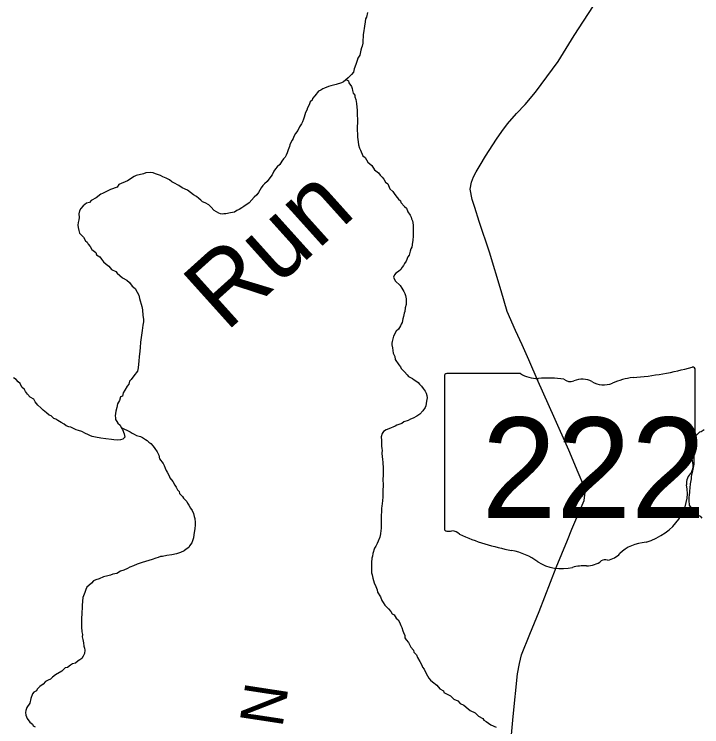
# Model space of a CAD drawing. Extents: x 0 to 34, y 0 to 22.
# Drawn here: x 4.746 to 5.649, y 14.474 to 15.409 of the extents above; entities that cross this region are included whole.
import ezdxf

# ---------------------------------------------------------------- set-up
doc = ezdxf.new("R2010")
doc.units = 0
for name, color, linetype in [('GM_X_Minor_River', 7, 'Continuous'), ('GM_X_Minor_River_Text', 7, 'Continuous'), ('GM_X_State_Location', 7, 'Continuous'), ('GM_X_State_Route', 7, 'Continuous'), ('GM_X_State_Shield', 7, 'Continuous'), ('GM_X_Township_Road_Text', 7, 'Continuous')]:
    doc.layers.add(name, color=color, linetype=linetype)

msp = doc.modelspace()

# ---------------------------------------------------------------- linework, layer by layer
at = {"layer": 'GM_X_Minor_River'}
for points in [[(5.20985, 15.4114), (5.20861, 15.40534), (5.20743, 15.40308), (5.20699, 15.39929), (5.20613, 15.3936), (5.20485, 15.38488), (5.20443, 15.38261), (5.20437, 15.37918), (5.20393, 15.37577), (5.20386, 15.37121), (5.20303, 15.36742), (5.20223, 15.36515), (5.20142, 15.36213), (5.19979, 15.35569), (5.19744, 15.35155), (5.19625, 15.34853), (5.19505, 15.34475), (5.19344, 15.33983), (5.19227, 15.33757), (5.19144, 15.33341), (5.1891, 15.33002), (5.18679, 15.32816), (5.18447, 15.32592), (5.181, 15.32294), (5.1783, 15.32071), (5.17561, 15.31924), (5.16873, 15.31707), (5.16186, 15.31529), (5.1588, 15.31421), (5.15344, 15.31202), (5.15115, 15.3113), (5.14845, 15.30944), (5.14539, 15.30836), (5.14073, 15.30236), (5.13763, 15.29861), (5.13721, 15.29633), (5.13451, 15.2941), (5.1333, 15.29032), (5.13134, 15.28655), (5.13015, 15.28353), (5.12857, 15.28014), (5.12695, 15.27408), (5.12576, 15.27144), (5.12457, 15.26804), (5.12338, 15.2654), (5.12065, 15.26126), (5.1183, 15.25674), (5.11518, 15.25261), (5.11322, 15.24885), (5.11241, 15.2462), (5.11086, 15.24394), (5.10889, 15.24018), (5.10809, 15.23791), (5.10768, 15.23564), (5.1065, 15.23337), (5.1057, 15.23111), (5.10449, 15.22732), (5.1033, 15.22431), (5.10174, 15.22167), (5.0998, 15.21942), (5.09747, 15.21642), (5.09473, 15.21191), (5.09126, 15.20893), (5.08931, 15.2063), (5.08698, 15.2033), (5.08462, 15.1984), (5.08306, 15.19614), (5.07801, 15.18977), (5.07454, 15.18679), (5.0726, 15.18454), (5.07027, 15.18154), (5.06674, 15.17514), (5.06441, 15.17214), (5.06094, 15.16915), (5.05435, 15.16167), (5.04742, 15.15684), (5.04473, 15.15499), (5.04127, 15.15277), (5.03821, 15.15168), (5.03513, 15.14945), (5.02979, 15.14841)], [(5.18162, 15.32347), (5.18516, 15.32173), (5.18549, 15.31906), (5.18884, 15.31444), (5.18993, 15.31176), (5.19027, 15.30909), (5.19135, 15.30565), (5.19321, 15.30296), (5.19355, 15.30067), (5.19463, 15.29723), (5.19569, 15.29227), (5.19598, 15.28732), (5.1963, 15.28351), (5.1966, 15.27894), (5.19656, 15.27628), (5.19687, 15.27209), (5.19661, 15.25651), (5.19692, 15.25232), (5.19683, 15.24738), (5.19718, 15.24509), (5.19819, 15.23785), (5.19926, 15.23365), (5.20074, 15.23096), (5.20403, 15.2233), (5.20703, 15.22097), (5.21036, 15.2152), (5.2156, 15.21055), (5.21931, 15.20478), (5.22457, 15.20089), (5.2268, 15.1978), (5.22942, 15.19548), (5.23165, 15.19278), (5.23349, 15.18894), (5.23649, 15.18661), (5.23942, 15.18009), (5.24317, 15.17661), (5.24502, 15.17391), (5.24725, 15.17083), (5.2506, 15.16659), (5.25323, 15.16426), (5.25395, 15.16197), (5.25842, 15.15695), (5.26105, 15.15462), (5.26287, 15.15002), (5.26621, 15.1454), (5.26731, 15.14272), (5.26765, 15.14043), (5.26913, 15.13813), (5.26948, 15.13584), (5.26979, 15.13203), (5.2701, 15.12784), (5.26994, 15.11834), (5.26946, 15.11226), (5.26904, 15.10999), (5.26817, 15.10354), (5.26699, 15.10128), (5.26618, 15.09825), (5.26457, 15.09296), (5.26301, 15.0907), (5.26064, 15.08504), (5.25869, 15.08203), (5.25712, 15.0794), (5.25556, 15.07715), (5.25399, 15.07413), (5.25091, 15.07152), (5.24707, 15.06931), (5.24551, 15.06705), (5.24394, 15.06404), (5.24614, 15.05944), (5.25288, 15.05324), (5.2551, 15.04977), (5.25769, 15.04516), (5.25916, 15.04248), (5.25988, 15.04018), (5.26057, 15.03561), (5.26089, 15.03218), (5.26082, 15.02838), (5.25961, 15.02384), (5.25914, 15.0189), (5.25835, 15.01663), (5.25714, 15.01247), (5.25633, 15.00944), (5.25548, 15.00452), (5.2543, 15.00226), (5.25312, 15), (5.25077, 14.99585), (5.24769, 14.99325), (5.24415, 14.98646), (5.24252, 14.97965), (5.2421, 14.97737), (5.24206, 14.97509), (5.24276, 14.97128), (5.24378, 14.96441), (5.24598, 14.95981), (5.2463, 14.956), (5.25113, 14.94907), (5.25336, 14.94637), (5.25408, 14.94408), (5.25858, 14.93982), (5.26193, 14.93596), (5.26379, 14.93364)], [(5.02979, 15.14841), (5.02407, 15.14737), (5.02141, 15.14703), (5.01912, 15.14669), (5.01685, 15.14711), (5.01458, 15.14791), (5.01157, 15.14987), (5.00856, 15.15144), (5.00408, 15.15646), (5.00146, 15.15917), (4.99656, 15.16154), (4.99316, 15.16312), (4.99092, 15.16506), (4.9883, 15.16739), (4.9853, 15.1701), (4.98153, 15.17207), (4.97365, 15.17829), (4.96648, 15.18146), (4.96196, 15.1842), (4.95556, 15.18773), (4.95293, 15.1893), (4.94992, 15.19164), (4.9454, 15.194), (4.94087, 15.19597), (4.93786, 15.19755), (4.93408, 15.19876), (4.93143, 15.19994), (4.92841, 15.20114), (4.925, 15.20158), (4.91891, 15.20092), (4.91585, 15.19984), (4.90593, 15.19773), (4.90362, 15.19625), (4.89478, 15.1907), (4.88329, 15.18558), (4.88095, 15.1822), (4.87216, 15.17931), (4.86717, 15.17636), (4.8618, 15.17379), (4.85951, 15.17307), (4.85335, 15.16824), (4.84683, 15.16493), (4.84488, 15.1623), (4.84068, 15.16123), (4.83644, 15.15789), (4.83334, 15.15414), (4.83177, 15.15112), (4.83094, 15.14733), (4.83124, 15.14239), (4.83081, 15.13935), (4.82999, 15.13594), (4.82955, 15.13253), (4.82988, 15.12948), (4.83057, 15.12529), (4.83166, 15.12185), (4.83689, 15.11643), (4.83947, 15.11182), (4.84172, 15.10988), (4.8432, 15.10757), (4.84581, 15.10449), (4.84802, 15.10026), (4.8529, 15.09638), (4.85399, 15.09332), (4.85812, 15.09058), (4.86036, 15.08788), (4.86296, 15.08403), (4.8667, 15.08092), (4.87009, 15.07858), (4.87382, 15.07433), (4.87947, 15.07157), (4.88096, 15.06927), (4.88808, 15.06306), (4.89373, 15.05991), (4.8971, 15.0572), (4.90082, 15.05219), (4.90457, 15.04908), (4.90715, 15.04447), (4.90936, 15.04025), (4.91043, 15.03605), (4.91114, 15.03299), (4.91258, 15.0284), (4.91367, 15.02534), (4.91436, 15.02115), (4.91499, 15.01353), (4.91568, 15.00896), (4.91562, 15.00553), (4.91478, 15.00099), (4.91391, 14.99416), (4.91262, 14.98505), (4.91175, 14.9786), (4.91125, 14.97177), (4.91079, 14.96683), (4.9099, 14.95924), (4.90944, 14.95431), (4.90852, 14.9452), (4.90769, 14.94065), (4.90302, 14.93465), (4.89952, 14.92976), (4.8972, 14.92752), (4.89637, 14.92335), (4.89405, 14.92073)], [(4.89405, 14.92073), (4.8913, 14.91546), (4.88896, 14.91208), (4.88813, 14.90791), (4.88545, 14.90681), (4.88423, 14.90227), (4.88305, 14.90001), (4.88149, 14.89776), (4.88065, 14.89283), (4.87943, 14.88791), (4.87857, 14.88184), (4.87891, 14.87955), (4.87887, 14.87727), (4.88073, 14.87457), (4.88183, 14.87227), (4.8852, 14.86955), (4.8863, 14.86687), (4.88815, 14.86418), (4.89034, 14.85843), (4.89102, 14.85386), (4.88832, 14.85124), (4.88564, 14.85053), (4.88184, 14.85022), (4.87651, 14.85031), (4.87386, 14.85074), (4.86627, 14.85163), (4.85944, 14.85251), (4.85262, 14.85377), (4.84846, 14.85499), (4.84506, 14.85618), (4.84242, 14.85737), (4.8394, 14.85857), (4.8345, 14.86132), (4.83034, 14.86253), (4.82732, 14.86372), (4.82279, 14.86571), (4.82015, 14.86689), (4.8175, 14.8677), (4.8141, 14.8689), (4.81147, 14.87085), (4.80733, 14.8732), (4.80319, 14.87594), (4.80056, 14.8775), (4.79792, 14.87869), (4.79417, 14.8818), (4.79191, 14.88298), (4.78815, 14.88571), (4.78403, 14.88958), (4.78066, 14.8923), (4.77692, 14.89617), (4.77319, 14.90042), (4.77173, 14.90387), (4.76683, 14.90662), (4.76348, 14.91048), (4.76087, 14.91395), (4.7594, 14.91664), (4.75603, 14.91974), (4.75344, 14.92435), (4.7512, 14.92667), (4.74821, 14.92976), (4.74482, 14.93172)], [(5.26379, 14.93364), (5.26644, 14.93245), (5.26907, 14.93089), (5.27132, 14.92933), (5.27358, 14.92815), (5.27659, 14.92581), (5.27845, 14.9235), (5.28107, 14.92079), (5.2833, 14.91771), (5.2859, 14.91424), (5.287, 14.91194), (5.28809, 14.90888), (5.28841, 14.90545), (5.28758, 14.90128), (5.28672, 14.89521), (5.28592, 14.89294), (5.2828, 14.88843), (5.27855, 14.88395), (5.27471, 14.88173), (5.27009, 14.87877), (5.26627, 14.8777), (5.2632, 14.87585), (5.25785, 14.87404), (5.25515, 14.87181), (5.25133, 14.87073), (5.24865, 14.86964), (5.24635, 14.86854), (5.23793, 14.86488), (5.23448, 14.86342), (5.23102, 14.8612), (5.22908, 14.85857), (5.22787, 14.85441), (5.22816, 14.84946), (5.22842, 14.84223), (5.22875, 14.83918), (5.22908, 14.83652), (5.22903, 14.83348), (5.22932, 14.82777), (5.22966, 14.82548), (5.23033, 14.82014), (5.2306, 14.81367), (5.23049, 14.80721), (5.23045, 14.80455), (5.23034, 14.79809), (5.23061, 14.79162), (5.23057, 14.78896), (5.23013, 14.78554), (5.22996, 14.77528), (5.22905, 14.76654), (5.229, 14.76388), (5.22856, 14.76009), (5.22852, 14.75781), (5.22801, 14.74983), (5.22792, 14.74451), (5.22788, 14.74223), (5.22774, 14.73424), (5.22731, 14.73121), (5.22686, 14.72703), (5.22603, 14.72286), (5.22404, 14.7172), (5.22285, 14.71455), (5.22089, 14.71079), (5.21932, 14.70815), (5.21693, 14.70135), (5.21648, 14.69755), (5.21568, 14.6949), (5.21521, 14.68959), (5.21514, 14.68541), (5.21505, 14.68046), (5.21536, 14.67589), (5.21607, 14.67322), (5.21714, 14.66902), (5.21855, 14.66253), (5.22076, 14.65792), (5.22259, 14.65371), (5.22329, 14.65027), (5.22699, 14.64412), (5.22881, 14.63953), (5.23067, 14.63683), (5.23289, 14.63337), (5.23513, 14.63105), (5.23738, 14.62873), (5.24073, 14.62487), (5.24259, 14.62217), (5.24484, 14.62061), (5.24781, 14.61638), (5.25043, 14.61405), (5.2519, 14.61098), (5.25373, 14.60676), (5.25521, 14.60408), (5.25628, 14.59987), (5.25738, 14.59757), (5.25883, 14.59336), (5.25916, 14.59032), (5.26064, 14.58801), (5.264, 14.58415), (5.26694, 14.57839), (5.27029, 14.57415), (5.27101, 14.57186), (5.27438, 14.56837), (5.27583, 14.56454)], [(4.8863, 14.86687), (4.89798, 14.86096), (4.90099, 14.85901), (4.90325, 14.85783), (4.90665, 14.85625), (4.91194, 14.85463), (4.9142, 14.85345), (4.91835, 14.8511), (4.9206, 14.84954), (4.92284, 14.84722), (4.92548, 14.84565), (4.92846, 14.84217), (4.93069, 14.83909), (4.93366, 14.83486), (4.93587, 14.83025), (4.93655, 14.82568), (4.94139, 14.81951), (4.94286, 14.81682), (4.94433, 14.81337), (4.94541, 14.81031), (4.9469, 14.808), (4.94948, 14.80339), (4.95019, 14.80072), (4.95429, 14.7957), (4.95687, 14.79072), (4.95873, 14.7884), (4.96019, 14.78495), (4.96244, 14.78263), (4.96277, 14.77996), (4.96689, 14.77609), (4.96837, 14.77378), (4.97062, 14.77184), (4.97248, 14.76952), (4.97358, 14.76722), (4.97544, 14.76453), (4.97728, 14.76069), (4.97951, 14.75761), (4.98134, 14.75378), (4.98204, 14.74996), (4.98313, 14.74728), (4.98342, 14.74195), (4.98337, 14.73853), (4.98329, 14.73397), (4.98201, 14.72562), (4.98118, 14.72183), (4.97917, 14.71503), (4.97606, 14.71128), (4.97526, 14.70901), (4.97181, 14.70679), (4.96911, 14.70493), (4.96451, 14.70235), (4.95916, 14.70093), (4.95305, 14.69951), (4.94619, 14.69849), (4.94086, 14.69744), (4.93819, 14.69711), (4.93513, 14.69602), (4.93169, 14.69494), (4.9271, 14.69312), (4.91411, 14.68955), (4.91143, 14.68845), (4.90722, 14.68701), (4.90262, 14.6848), (4.89766, 14.68337), (4.89459, 14.68152), (4.88999, 14.67932), (4.8854, 14.67788), (4.88079, 14.67492), (4.87545, 14.67387), (4.87239, 14.67279), (4.86895, 14.67208), (4.86323, 14.67067), (4.85748, 14.6681), (4.8529, 14.66666), (4.85021, 14.66519), (4.8475, 14.66219), (4.84365, 14.65922), (4.84133, 14.65698), (4.84014, 14.65396), (4.83855, 14.65018), (4.83616, 14.64338), (4.83569, 14.63844), (4.83523, 14.63313), (4.83515, 14.62856), (4.83471, 14.62515), (4.83465, 14.62135), (4.83419, 14.61679), (4.83408, 14.61033), (4.83441, 14.60728), (4.83437, 14.605), (4.83464, 14.59853), (4.83534, 14.59471), (4.83529, 14.59167), (4.83599, 14.58824), (4.83706, 14.58403), (4.83736, 14.57947), (4.83808, 14.57679), (4.83841, 14.57412), (4.83796, 14.56995)], [(5.6523, 14.86372), (5.64845, 14.86112), (5.64616, 14.8604), (5.64191, 14.85629), (5.6396, 14.85481), (5.63723, 14.84915), (5.6364, 14.84498), (5.63634, 14.84156), (5.63668, 14.83927), (5.63808, 14.83202), (5.63876, 14.82706), (5.63862, 14.8187), (5.63778, 14.81415), (5.63653, 14.80771), (5.63572, 14.80468), (5.6353, 14.80203), (5.63525, 14.79936), (5.634, 14.79254), (5.63353, 14.78723), (5.63308, 14.78305), (5.63304, 14.78077), (5.63262, 14.7785), (5.63217, 14.77432), (5.63211, 14.7709), (5.63239, 14.76481), (5.63462, 14.76173), (5.63723, 14.75864), (5.64056, 14.75364), (5.64396, 14.75206), (5.64697, 14.7501), (5.64921, 14.74778)], [(4.83796, 14.56995), (4.83639, 14.56655), (4.83482, 14.56354), (4.83212, 14.56168), (4.82982, 14.5602), (4.82634, 14.55722), (4.82252, 14.55615), (4.81984, 14.55467), (4.81599, 14.5517), (4.81293, 14.55099), (4.8083, 14.54651), (4.79986, 14.54209), (4.796, 14.53874), (4.79368, 14.53612), (4.79062, 14.53503), (4.78678, 14.5332), (4.78407, 14.52982), (4.77945, 14.52648), (4.77597, 14.52312), (4.77517, 14.52085), (4.77172, 14.51901), (4.76978, 14.51676), (4.76778, 14.51071), (4.76615, 14.50465), (4.76226, 14.49902), (4.76105, 14.49523), (4.76063, 14.49258), (4.76095, 14.48915), (4.76277, 14.48456), (4.7665, 14.47993), (4.76987, 14.4772), (4.77059, 14.47491), (4.77324, 14.47372)], [(5.27583, 14.56454), (5.27879, 14.55955), (5.28137, 14.55456), (5.28208, 14.55188), (5.28432, 14.54918), (5.28579, 14.54611), (5.28874, 14.54074), (5.29059, 14.53766), (5.29282, 14.53496), (5.29545, 14.53263), (5.30108, 14.52835), (5.30518, 14.52372), (5.3097, 14.52097), (5.31042, 14.51868), (5.31381, 14.5171), (5.31909, 14.51434), (5.32358, 14.51008), (5.32848, 14.50772), (5.33184, 14.50423), (5.33637, 14.50187), (5.34237, 14.4972), (5.345, 14.49525), (5.35141, 14.4921), (5.35589, 14.48746), (5.36155, 14.4847), (5.36265, 14.4824), (5.36605, 14.48081), (5.37205, 14.47615), (5.37885, 14.47336)]]:
    msp.add_lwpolyline(points, dxfattribs=at)
at = {"layer": 'GM_X_State_Route'}
msp.add_lwpolyline([(5.39693, 14.43968), (5.40148, 14.48699), (5.40714, 14.54311), (5.40966, 14.55663), (5.41209, 14.56822), (5.42313, 14.59538), (5.43535, 14.6249), (5.4579, 14.6828), (5.47266, 14.71887), (5.4783, 14.73303), (5.49467, 14.77069), (5.49589, 14.78155), (5.49424, 14.79027), (5.48659, 14.80772), (5.4743, 14.83679), (5.45479, 14.8811), (5.434, 14.92684), (5.42191, 14.95572), (5.41329, 14.97517), (5.40454, 14.99387), (5.39362, 15.01888), (5.38539, 15.04597), (5.37025, 15.09689), (5.35689, 15.13726), (5.35095, 15.15537), (5.34745, 15.16617), (5.34501, 15.17942), (5.34665, 15.18862), (5.34917, 15.1956), (5.35273, 15.20257), (5.35807, 15.21119), (5.36505, 15.22276), (5.3793, 15.24547), (5.38658, 15.25542), (5.39383, 15.26544), (5.40573, 15.27917), (5.4172, 15.29081), (5.43066, 15.30708), (5.4605, 15.3473), (5.48158, 15.38145), (5.51269, 15.42945)], dxfattribs=at)
at = {"layer": 'GM_X_State_Shield'}
for p, q in [((5.64066, 14.83777), (5.64066, 14.94245)), ((5.31107, 14.93405), (5.31107, 14.73393)), ((5.41084, 14.93749), (5.31432, 14.93749)), ((5.64063, 14.83779), (5.64066, 14.83777))]:
    msp.add_line(p, q, dxfattribs=at)
for centre, major_axis, start_param, end_param in [((5.52326, 15.21032), (0.34952, 0), 4.814394, 5.042369), ((5.637, 14.94288), (0.00367, 0), 6.141152, 7.989035), ((5.31485, 14.93447), (0.00382, 0), 1.712693, 3.28349), ((5.43383, 14.96072), (0.03703, 0), 4.042523, 4.731795), ((5.4461, 14.82514), (0.13295, 0), 1.404758, 1.657858), ((5.56784, 14.87637), (0.07032, 0), 1.699011, 2.107814), ((5.47629, 14.93551), (0.01068, 0), 3.836095, 5.185415), ((5.49197, 14.91238), (0.02221, 0), 0.950623, 2.079405), ((5.52064, 14.94411), (0.02672, 0), 4.081561, 5.145723), ((5.63981, 14.83008), (0.00568, 0), 1.883978, 3.671073), ((5.63674, 14.83736), (0.00393, 0), 5.05454, 6.418171), ((5.60369, 14.81685), (0.03409, 0), 5.934695, 6.695948), ((5.6538, 14.79396), (0.0248, 0), 2.387724, 3.262537), ((5.54283, 14.78064), (0.08742, 0), 5.101752, 6.440018), ((5.31488, 14.73349), (0.00385, 0), 3.00124, 4.508301), ((5.31547, 14.75396), (0.0294, 0), 4.665946, 4.897461), ((5.32148, 14.72238), (0.0106, 0), 0.519207, 1.627899), ((5.45531, 14.90218), (0.2524, 0), 4.195997, 4.488961), ((5.5797, 14.67774), (0.04788, 0), 1.647645, 2.488434), ((5.38006, 14.64402), (0.07897, 0), 0.823519, 1.323587), ((5.51903, 14.71453), (0.02824, 0), 4.937069, 5.64225), ((5.46547, 14.72139), (0.05011, 0), 4.026481, 4.996735), ((5.49809, 14.7064), (0.0267, 0), 4.691044, 5.507374), ((5.52224, 14.68702), (0.00752, 0), 1.147584, 2.315152), ((5.49443, 14.6522), (0.04118, 0), 1.495662, 1.94098)]:
    msp.add_ellipse(centre, major_axis=major_axis, ratio=0.8, start_param=start_param, end_param=end_param, dxfattribs=at)

# ---------------------------------------------------------------- texts
at = {"layer": 'GM_X_Minor_River_Text'}
msp.add_text('Run', height=0.094688, rotation=41.99771, dxfattribs=at).set_placement((5.02402, 14.99107))
at = {"layer": 'GM_X_State_Location'}
for s, p in [('s', (5.47216, 14.82068)), ('r', (5.47215, 14.82068))]:
    msp.add_text(s, height=0.000189, dxfattribs=at).set_placement(p)
msp.add_text('222', height=0.000189, rotation=0.00001, dxfattribs=at).set_placement((5.4053, 14.8069))
at = {"layer": 'GM_X_State_Shield'}
msp.add_text('222', height=0.131836, dxfattribs=at).set_placement((5.36007, 14.74804))
at = {"layer": 'GM_X_Township_Road_Text'}
msp.add_text('N', height=0.05682, rotation=81.31144, dxfattribs=at).set_placement((5.09802, 14.47143))

doc.saveas('drawing.dxf')
